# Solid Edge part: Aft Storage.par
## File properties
Author: m_hel
Template: Iso Metric Part.par
Last saved by: m_hel
Revision: 2
Application: Solid Edge
Username: m_hel
Accuracy: 0,990
Material: Glass Fiber
Face Style: White (dull)
Fill Style: ANSI36(Marble)
Virtual Style: ANSI36(Marble)
Grouping: Uncategorized
LibraryName: Custom Materials
Coef. of Thermal Exp: 0.0
Thermal Conductivity: 0.0
Specific Heat: 0.0
Modulus of Elasticity: 0.0
Poisson's Ratio: 0.0
Yield Stress: 0.0
Ultimate Stress: 0.0
Elongation: 0.0
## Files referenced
..\..\Redfisher18.asm
G:\OneDriveTemp\OneDrive\Dokumendid\TLÜ tööd\3D Modelleerimine\3d modelling\veesõiduk\Deck1.par
iduk\Deck1.par
iduk\Redfisher18.asm
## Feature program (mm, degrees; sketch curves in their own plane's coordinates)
sketch for "unnamed Protrusion 1" plane through (0, 0, 0) normal (0, 0, 1) x-axis (1, 0, 0)
  line (-30, 10) -> (-30, -420)
  arc centre (-20, -420) radius 10 from (-30, -420) to (-20, -430) ccw
  line (-20, -430) -> (960, -430)
  arc centre (960, -420) radius 10 from (970, -420) to (960, -430) cw
  line (970, -420) -> (970, 10)
  arc centre (960, 10) radius 10 from (970, 10) to (960, 20) ccw
  line (960, 20) -> (-20, 20)
  arc centre (-20, 10) radius 10 from (-20, 20) to (-30, 10) ccw
extrude "unnamed Protrusion 1" add finite 200 along -normal
thinwall "Thinwall_1"  Thickness = 50 mm
thinwall "Thinwall_2"  Thickness = 20 mm
fillet "Round_1" radius 30
sketch for "unnamed Cutout 1" plane through (0, 0, 0) normal (1, 0, 0) x-axis (0, 1, 0)
  line (40, -20) -> (40, 56.4047)
extrude "unnamed Cutout 1" cut through along +normal
fillet "Round_2" radius 30
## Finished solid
Body 1: solid body, 43 faces, 96 edges, 56 vertices.
  Faces by surface: cylinder 20, plane 15, blend 4, sphere 4
  Edges by curve: line 56, circle 32, ellipse 8
Bounding box of the edges (mm; curved faces can reach further): 1100.000 x 520.000 x 220.000, from (-80, -480, -220) to (1020, 40, 0).
Cylindrical faces by radius (mm): R10 x4, R30 x14, R60 x2
Spherical faces by radius (mm): R30 x4
Planar faces by outward normal: +x 3, +y 2, +z 2, -x 3, -y 3, -z 2
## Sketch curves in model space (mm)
arc centre (-20, 10, 0) radius 10 from (-20, 20, 0) through (-27.2737, 16.8624, 0) to (-30, 10, 0)
line (-30, 10, 0) -> (-30, -420, 0)
arc centre (-20, -420, 0) radius 10 from (-30, -420, 0) through (-26.8624, -427.2737, 0) to (-20, -430, 0)
line (-20, -430, 0) -> (960, -430, 0)
arc centre (960, -420, 0) radius 10 from (970, -420, 0) through (966.8624, -427.2737, 0) to (960, -430, 0)
line (970, -420, 0) -> (970, 10, 0)
arc centre (960, 10, 0) radius 10 from (970, 10, 0) through (966.8624, 17.2737, 0) to (960, 20, 0)
line (960, 20, 0) -> (-20, 20, 0)
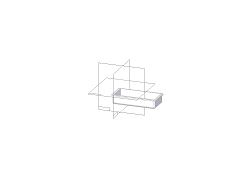
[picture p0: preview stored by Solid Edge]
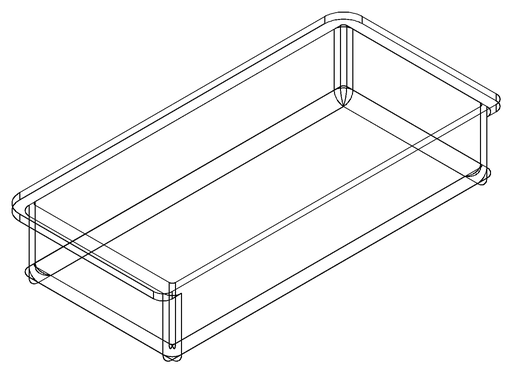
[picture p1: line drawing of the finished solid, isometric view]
